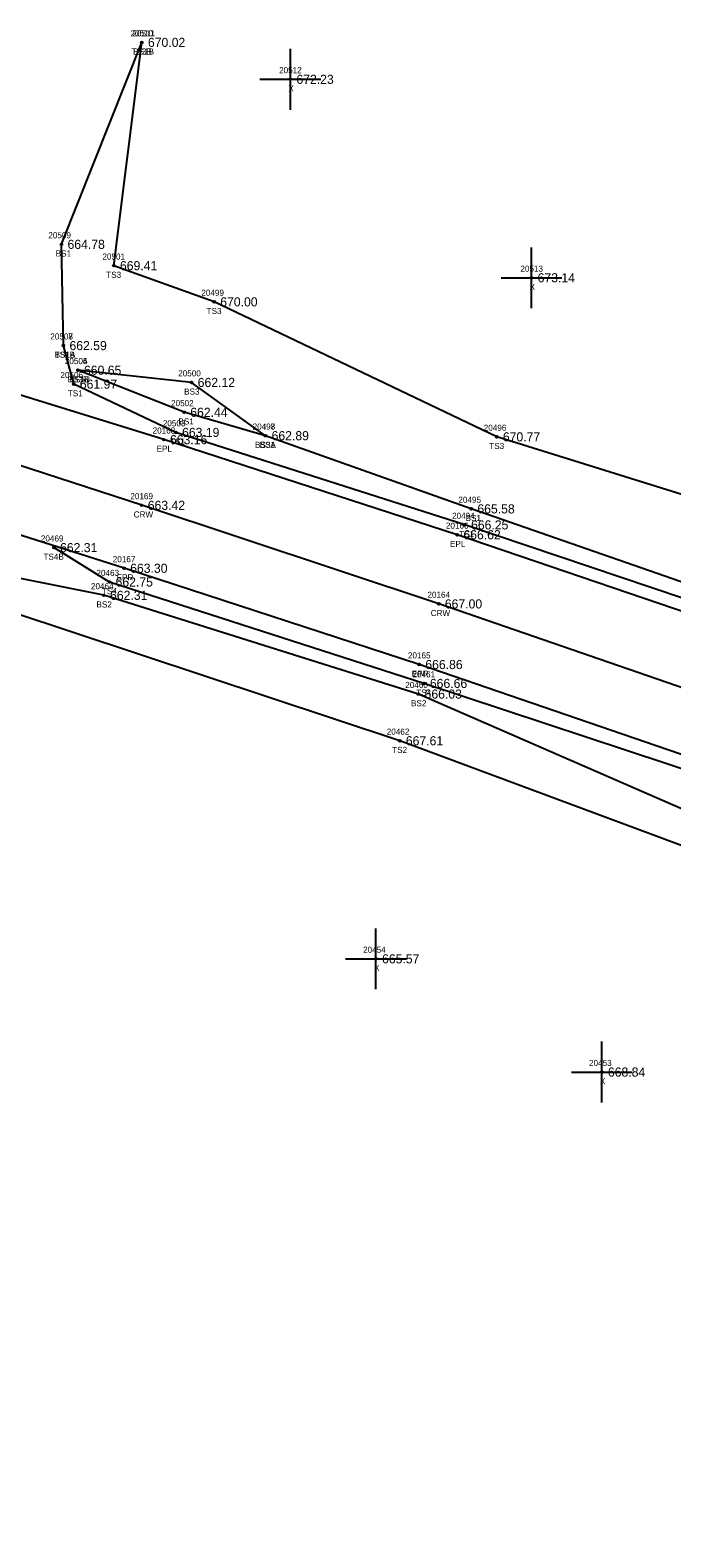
# Model space of a CAD drawing. Extents: x 1655675 to 1657082, y 1004080 to 1005193.
# Drawn here: x 1656556.3 to 1656661.8, y 1004388.9 to 1004636.9 of the extents above; entities that cross this region are included whole.
import ezdxf

# ---------------------------------------------------------------- set-up
doc = ezdxf.new("R2010")
doc.units = 0
for name, color, linetype in [('RD_DTM_BkLn1', 7, 'Continuous'), ('RD_DTM_BkLn2', 7, 'Continuous'), ('RD_DTM_BkLn_txCode', 7, 'Continuous'), ('RD_EX_Misc', 7, 'Continuous'), ('RD_EX_Misc_txCode', 7, 'Continuous'), ('RD_EX_Road', 7, 'Continuous'), ('RD_EX_Road_txCode', 7, 'Continuous'), ('RD_EX_TX_Misc_ELEV', 7, 'Continuous'), ('RD_EX_TX_Road_ELEV', 7, 'Continuous'), ('RD_HC_Survey_ELEV', 7, 'Continuous'), ('RD_HC_Survey_txCode', 7, 'Continuous'), ('RD_SMD_Locator', 7, 'Continuous')]:
    doc.layers.add(name, color=color, linetype=linetype)

msp = doc.modelspace()

# ---------------------------------------------------------------- linework, layer by layer
at = {"layer": 'RD_DTM_BkLn1'}
msp.add_lwpolyline([(1657061.44, 1004399.53), (1657012.07, 1004414.01), (1656963.11, 1004429.39), (1656914.21, 1004444.93), (1656865.73, 1004460.97), (1656817.07, 1004476.94), (1656768.62, 1004493.15), (1656720.24, 1004509.39), (1656671.72, 1004525.86), (1656623.45, 1004542.51), (1656574.61, 1004558.72), (1656526.43, 1004574.41), (1656478.09, 1004590.75), (1656429.6, 1004607.09), (1656401.58, 1004616.48)], dxfattribs=at)
at = {"layer": 'RD_DTM_BkLn2'}
for points in [[(1656561.74, 1004584.99), (1656561.42, 1004601.64), (1656574.64, 1004634.85)], [(1656797.39, 1004506.96), (1656776.31, 1004516.3), (1656728.84, 1004530.74), (1656712.25, 1004533.98), (1656700.64, 1004542.17), (1656680.31, 1004555.23), (1656632.99, 1004569.98), (1656586.53, 1004592.18), (1656570.04, 1004598.13), (1656574.64, 1004634.85)], [(1656803.54, 1004495.96), (1656773.89, 1004507.09), (1656726.18, 1004522.31), (1656711.1, 1004528.67), (1656673.78, 1004540.02), (1656627.76, 1004555.5), (1656580.25, 1004570.71), (1656563.44, 1004578.65), (1656561.74, 1004584.99)], [(1656789.27, 1004506.07), (1656774.83, 1004510.56), (1656727.19, 1004526.68), (1656712.01, 1004530.19), (1656706.84, 1004533.13), (1656674.46, 1004542.26), (1656628.8, 1004558.14), (1656594.97, 1004570.17), (1656581.6, 1004574.02), (1656564.13, 1004580.94)], [(1656594.97, 1004570.17), (1656582.82, 1004578.93), (1656564.13, 1004580.94)], [(1656916.22, 1004427.16), (1656860.73, 1004444.79), (1656812.26, 1004457.45), (1656804.38, 1004456.52), (1656762.93, 1004472.17), (1656714, 1004488.45), (1656666.66, 1004507.38), (1656620.12, 1004527.68), (1656568.41, 1004543.92), (1656526.96, 1004552.22)], [(1656917.58, 1004430.1), (1656861.23, 1004447.04), (1656812.34, 1004463.2), (1656764.22, 1004476.47), (1656716.73, 1004495.56), (1656667.72, 1004513.97), (1656620.99, 1004529.43), (1656569.32, 1004546.11), (1656560.19, 1004551.77)], [(1656877.14, 1004434.43), (1656862.63, 1004439.86), (1656832.96, 1004433.22), (1656804.97, 1004442.37), (1656761.39, 1004459.38), (1656711.4, 1004477.11), (1656669.22, 1004500.61), (1656617.04, 1004520), (1656542.14, 1004544.84), (1656525.4, 1004509.94)]]:
    msp.add_lwpolyline(points, dxfattribs=at)
at = {"layer": 'RD_EX_Misc'}
for p, q in [((1656599.05, 1004623.78), (1656599.05, 1004633.78)), ((1656594.05, 1004628.78), (1656604.05, 1004628.78)), ((1656638.71, 1004591.14), (1656638.71, 1004601.14)), ((1656633.71, 1004596.14), (1656643.71, 1004596.14)), ((1656613.13, 1004479.14), (1656613.13, 1004489.14)), ((1656608.13, 1004484.14), (1656618.13, 1004484.14)), ((1656650.26, 1004460.52), (1656650.26, 1004470.52)), ((1656645.26, 1004465.52), (1656655.26, 1004465.52))]:
    msp.add_line(p, q, dxfattribs=at)
at = {"layer": 'RD_EX_Road'}
for points in [[(1657064.39, 1004409.09), (1657015.67, 1004424.64), (1656965.82, 1004440.6), (1656917.99, 1004455.95), (1656868.5, 1004471.86), (1656826.53, 1004486.06), (1656801.74, 1004494.51), (1656772.14, 1004504.27), (1656723.45, 1004520.92), (1656674.94, 1004537.34), (1656626.5, 1004553.88), (1656578.27, 1004569.52), (1656529.18, 1004584.75), (1656481.5, 1004600.51), (1656432.67, 1004617.14), (1656404.34, 1004625.82)], [(1657057.77, 1004388.92), (1657009.7, 1004404.08), (1656958.18, 1004419.84), (1656956.49, 1004419.67), (1656924.83, 1004429.55), (1656916.51, 1004432.8), (1656911.19, 1004434.68), (1656862.46, 1004450.21), (1656813.53, 1004466.42), (1656765.51, 1004482.33), (1656716.81, 1004499.14), (1656668.6, 1004515.93), (1656620.24, 1004532.54), (1656571.72, 1004548.37), (1656523.3, 1004563.77), (1656474.37, 1004580.29), (1656426.43, 1004596.82), (1656398.22, 1004606.78)]]:
    msp.add_lwpolyline(points, dxfattribs=at)
at = {"layer": 'RD_SMD_Locator'}
for centre in [(1656574.64, 1004634.85), (1656574.64, 1004634.85), (1656599.05, 1004628.78), (1656561.42, 1004601.64), (1656570.04, 1004598.13), (1656638.71, 1004596.14), (1656586.53, 1004592.18), (1656561.74, 1004584.99), (1656561.74, 1004584.99), (1656564.13, 1004580.94), (1656564.13, 1004580.94), (1656582.82, 1004578.93), (1656563.44, 1004578.65), (1656581.6, 1004574.02), (1656578.27, 1004569.52), (1656580.25, 1004570.71), (1656594.97, 1004570.17), (1656594.97, 1004570.17), (1656632.99, 1004569.98), (1656574.61, 1004558.72), (1656628.8, 1004558.14), (1656627.76, 1004555.5), (1656560.19, 1004551.77), (1656626.5, 1004553.88), (1656571.72, 1004548.37), (1656569.32, 1004546.11), (1656568.41, 1004543.92), (1656623.45, 1004542.51), (1656620.24, 1004532.54), (1656620.99, 1004529.43), (1656620.12, 1004527.68), (1656617.04, 1004520), (1656613.13, 1004484.14), (1656650.26, 1004465.52)]:
    msp.add_circle(centre, 0.15, dxfattribs=at)

# ---------------------------------------------------------------- texts
at = {"layer": 'RD_DTM_BkLn_txCode'}
for s, p in [('20510', (1656572.77, 1004635.85)), ('20511', (1656573.09, 1004635.85)), ('TS3B', (1656572.93, 1004632.85)), ('BS1B', (1656573.22, 1004632.85)), ('20509', (1656559.27, 1004602.64)), ('BS1', (1656560.48, 1004599.64)), ('20501', (1656568.16, 1004599.13)), ('TS3', (1656568.79, 1004596.13)), ('20499', (1656584.42, 1004593.18)), ('TS3', (1656585.29, 1004590.18)), ('20507', (1656559.59, 1004585.99)), ('20508', (1656559.59, 1004585.99)), ('TS1B', (1656560.31, 1004582.99)), ('BS1A', (1656560.31, 1004582.99)), ('20504', (1656561.98, 1004581.94)), ('20505', (1656561.98, 1004581.94)), ('20506', (1656561.26, 1004579.65)), ('BS3B', (1656562.43, 1004578.94)), ('BS1B', (1656562.72, 1004578.94)), ('20500', (1656580.62, 1004579.93)), ('TS1', (1656562.48, 1004576.65)), ('BS3', (1656581.59, 1004576.93)), ('20502', (1656579.44, 1004575.02)), ('20503', (1656578.09, 1004571.71)), ('BS1', (1656580.66, 1004572.02)), ('20497', (1656592.85, 1004571.17)), ('20498', (1656592.85, 1004571.17)), ('20496', (1656630.85, 1004570.98)), ('TS1', (1656579.29, 1004568.71)), ('BS3A', (1656593.25, 1004568.17)), ('BS1', (1656594.02, 1004568.17)), ('TS3', (1656631.75, 1004567.98)), ('20495', (1656626.68, 1004559.14)), ('20494', (1656625.64, 1004556.5)), ('BS1', (1656627.86, 1004556.14)), ('TS1', (1656626.8, 1004553.5)), ('20469', (1656558.04, 1004552.77)), ('TS4B', (1656558.47, 1004549.77)), ('20463', (1656567.18, 1004547.11)), ('20464', (1656566.27, 1004544.92)), ('TS4', (1656568.08, 1004544.11)), ('BS2', (1656567.18, 1004541.92)), ('20460', (1656617.94, 1004528.68)), ('20461', (1656619.13, 1004530.43)), ('TS4', (1656619.75, 1004527.43)), ('BS2', (1656618.89, 1004525.68)), ('20462', (1656614.9, 1004521)), ('TS2', (1656615.8, 1004518))]:
    msp.add_text(s, height=1, dxfattribs=at).set_placement(p)
at = {"layer": 'RD_EX_Misc_txCode'}
for s, p in [('20512', (1656597.21, 1004629.78)), ('X', (1656598.73, 1004626.78)), ('20513', (1656636.87, 1004597.14)), ('X', (1656638.39, 1004594.14)), ('20454', (1656611.01, 1004485.14)), ('X', (1656612.82, 1004482.14)), ('20453', (1656648.15, 1004466.52)), ('X', (1656649.95, 1004463.52))]:
    msp.add_text(s, height=1, dxfattribs=at).set_placement(p)
at = {"layer": 'RD_EX_Road_txCode'}
for s, p in [('20168', (1656576.41, 1004570.52)), ('EPL', (1656577.06, 1004567.52)), ('20166', (1656624.62, 1004554.88)), ('EPL', (1656625.3, 1004551.88)), ('20167', (1656569.86, 1004549.37)), ('EPR', (1656570.49, 1004546.37)), ('20165', (1656618.38, 1004533.54)), ('EPR', (1656619.01, 1004530.54))]:
    msp.add_text(s, height=1, dxfattribs=at).set_placement(p)
at = {"layer": 'RD_EX_TX_Misc_ELEV'}
for s, p in [('670.02', (1656575.64, 1004634.1)), ('670.02', (1656575.64, 1004634.1)), ('672.23', (1656600.05, 1004628.03)), ('664.78', (1656562.42, 1004600.89)), ('669.41', (1656571.04, 1004597.38)), ('673.14', (1656639.71, 1004595.39)), ('670.00', (1656587.53, 1004591.43)), ('662.59', (1656562.74, 1004584.24)), ('662.59', (1656562.74, 1004584.24)), ('660.65', (1656565.13, 1004580.19)), ('660.65', (1656565.13, 1004580.19)), ('661.97', (1656564.44, 1004577.9)), ('662.12', (1656583.82, 1004578.18)), ('662.44', (1656582.6, 1004573.27)), ('663.19', (1656581.25, 1004569.96)), ('662.89', (1656595.97, 1004569.42)), ('662.89', (1656595.97, 1004569.42)), ('670.77', (1656633.99, 1004569.23)), ('665.58', (1656629.8, 1004557.39)), ('666.25', (1656628.76, 1004554.75)), ('662.31', (1656561.19, 1004551.02)), ('662.75', (1656570.32, 1004545.36)), ('662.31', (1656569.41, 1004543.17)), ('666.66', (1656621.99, 1004528.68)), ('666.03', (1656621.12, 1004526.93)), ('667.61', (1656618.04, 1004519.25)), ('665.57', (1656614.13, 1004483.39)), ('668.84', (1656651.26, 1004464.77))]:
    msp.add_text(s, height=1.5, dxfattribs=at).set_placement(p)
at = {"layer": 'RD_EX_TX_Road_ELEV'}
for s, p in [('663.16', (1656579.27, 1004568.77)), ('666.62', (1656627.5, 1004553.13)), ('663.30', (1656572.72, 1004547.62)), ('666.86', (1656621.24, 1004531.79))]:
    msp.add_text(s, height=1.5, dxfattribs=at).set_placement(p)
at = {"layer": 'RD_HC_Survey_ELEV'}
for s, p in [('663.42', (1656575.61, 1004557.97)), ('667.00', (1656624.45, 1004541.76))]:
    msp.add_text(s, height=1.5, dxfattribs=at).set_placement(p)
at = {"layer": 'RD_HC_Survey_txCode'}
for s, p in [('20169', (1656572.75, 1004559.72)), ('CRW', (1656573.3, 1004556.72)), ('20164', (1656621.59, 1004543.51)), ('CRW', (1656622.13, 1004540.51))]:
    msp.add_text(s, height=1, dxfattribs=at).set_placement(p)

doc.saveas('drawing.dxf')
